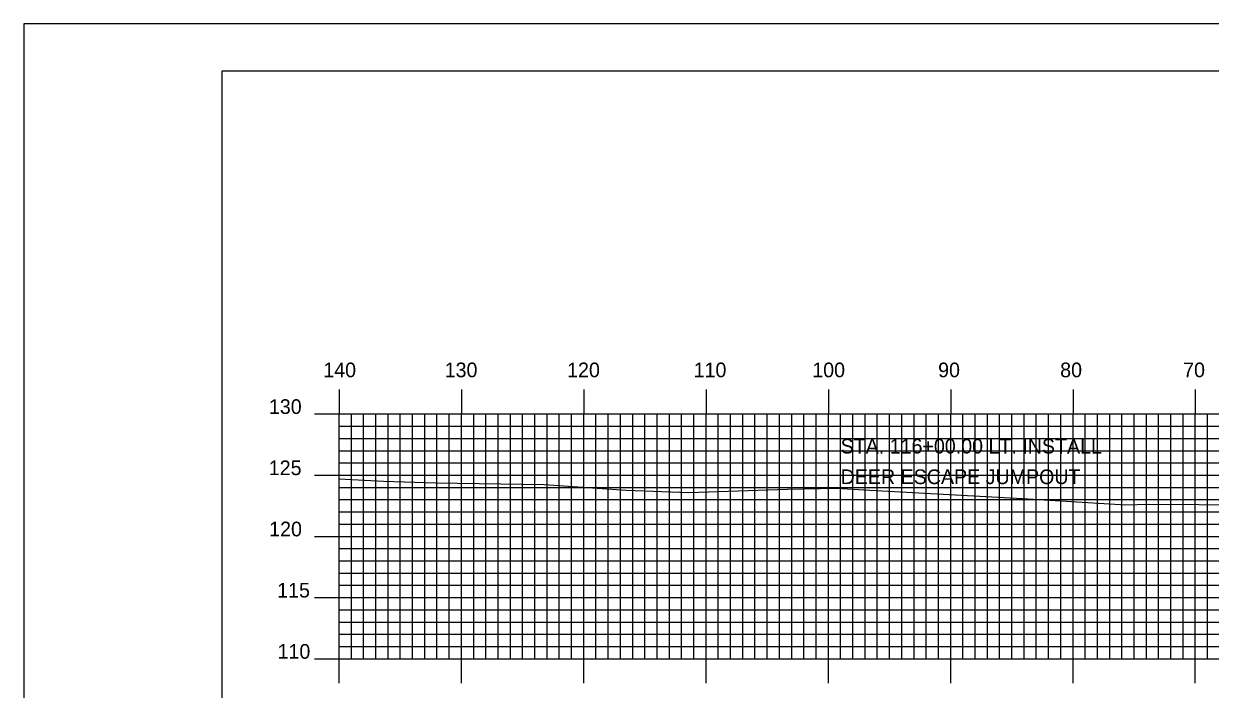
# Model space of a CAD drawing. Extents: x 1770842 to 1771185, y 442591 to 442811.
# Drawn here: x 1770841.8 to 1770938.8, y 442756.2 to 442810.5 of the extents above; entities that cross this region are included whole.
import ezdxf

# ---------------------------------------------------------------- set-up
doc = ezdxf.new("R2010")
doc.units = 0
for name, color, linetype in [('BORDER', 7, 'Continuous'), ('D_Text_Standard', 7, 'Continuous'), ('H_V ANNOTATION', 7, 'Continuous'), ('MAJOR', 7, 'Continuous'), ('MINOR', 7, 'Continuous'), ('PLOT BOUNDARY', 7, 'Continuous'), ('S_Roadway_Centerline', 7, 'Continuous')]:
    doc.layers.add(name, color=color, linetype=linetype)

msp = doc.modelspace()

# ---------------------------------------------------------------- linework, layer by layer
at = {"layer": 'BORDER'}
msp.add_lwpolyline([(1770857.954, 442596.665), (1771177.954, 442596.665), (1771177.954, 442806.665), (1770857.954, 442806.665)], close=True, dxfattribs=at)
at = {"layer": 'MAJOR'}
for p, q in [((1770867.554, 442780.669), (1770867.554, 442778.665)), ((1770877.554, 442780.669), (1770877.554, 442778.665)), ((1770887.554, 442780.669), (1770887.554, 442778.665)), ((1770897.554, 442780.669), (1770897.554, 442778.665)), ((1770907.554, 442780.669), (1770907.554, 442778.665)), ((1770917.554, 442780.669), (1770917.554, 442778.665)), ((1770927.554, 442780.669), (1770927.554, 442778.665)), ((1770937.554, 442780.669), (1770937.554, 442778.665)), ((1770865.55, 442778.665), (1770867.554, 442778.665)), ((1770867.554, 442778.665), (1771147.554, 442778.665)), ((1770867.554, 442758.665), (1770867.554, 442778.665)), ((1770867.554, 442758.665), (1770867.554, 442778.665)), ((1770867.554, 442778.665), (1771147.554, 442778.665)), ((1770877.554, 442758.665), (1770877.554, 442778.665)), ((1770887.554, 442758.665), (1770887.554, 442778.665)), ((1770897.554, 442758.665), (1770897.554, 442778.665)), ((1770907.554, 442758.665), (1770907.554, 442778.665)), ((1770917.554, 442758.665), (1770917.554, 442778.665)), ((1770927.554, 442758.665), (1770927.554, 442778.665)), ((1770937.554, 442758.665), (1770937.554, 442778.665)), ((1770865.55, 442773.665), (1770867.554, 442773.665)), ((1770867.554, 442773.665), (1771147.554, 442773.665)), ((1770865.55, 442768.665), (1770867.554, 442768.665)), ((1770867.554, 442768.665), (1771147.554, 442768.665)), ((1770865.55, 442763.665), (1770867.554, 442763.665)), ((1770867.554, 442763.665), (1771147.554, 442763.665)), ((1770865.55, 442758.665), (1770867.554, 442758.665)), ((1770867.554, 442758.665), (1771147.554, 442758.665)), ((1770867.554, 442758.665), (1771147.554, 442758.665)), ((1770867.554, 442756.661), (1770867.554, 442758.665)), ((1770877.554, 442756.661), (1770877.554, 442758.665)), ((1770887.554, 442756.661), (1770887.554, 442758.665)), ((1770897.554, 442756.661), (1770897.554, 442758.665)), ((1770907.554, 442756.661), (1770907.554, 442758.665)), ((1770917.554, 442756.661), (1770917.554, 442758.665)), ((1770927.554, 442756.661), (1770927.554, 442758.665)), ((1770937.554, 442756.661), (1770937.554, 442758.665))]:
    msp.add_line(p, q, dxfattribs=at)
at = {"layer": 'MINOR'}
for p, q in [((1770868.554, 442758.665), (1770868.554, 442778.665)), ((1770869.554, 442758.665), (1770869.554, 442778.665)), ((1770870.554, 442758.665), (1770870.554, 442778.665)), ((1770871.554, 442758.665), (1770871.554, 442778.665)), ((1770872.554, 442758.665), (1770872.554, 442778.665)), ((1770873.554, 442758.665), (1770873.554, 442778.665)), ((1770874.554, 442758.665), (1770874.554, 442778.665)), ((1770875.554, 442758.665), (1770875.554, 442778.665)), ((1770876.554, 442758.665), (1770876.554, 442778.665)), ((1770878.554, 442758.665), (1770878.554, 442778.665)), ((1770879.554, 442758.665), (1770879.554, 442778.665)), ((1770880.554, 442758.665), (1770880.554, 442778.665)), ((1770881.554, 442758.665), (1770881.554, 442778.665)), ((1770882.554, 442758.665), (1770882.554, 442778.665)), ((1770883.554, 442758.665), (1770883.554, 442778.665)), ((1770884.554, 442758.665), (1770884.554, 442778.665)), ((1770885.554, 442758.665), (1770885.554, 442778.665)), ((1770886.554, 442758.665), (1770886.554, 442778.665)), ((1770888.554, 442758.665), (1770888.554, 442778.665)), ((1770889.554, 442758.665), (1770889.554, 442778.665)), ((1770890.554, 442758.665), (1770890.554, 442778.665)), ((1770891.554, 442758.665), (1770891.554, 442778.665)), ((1770892.554, 442758.665), (1770892.554, 442778.665)), ((1770893.554, 442758.665), (1770893.554, 442778.665)), ((1770894.554, 442758.665), (1770894.554, 442778.665)), ((1770895.554, 442758.665), (1770895.554, 442778.665)), ((1770896.554, 442758.665), (1770896.554, 442778.665)), ((1770898.554, 442758.665), (1770898.554, 442778.665)), ((1770899.554, 442758.665), (1770899.554, 442778.665)), ((1770900.554, 442758.665), (1770900.554, 442778.665)), ((1770901.554, 442758.665), (1770901.554, 442778.665)), ((1770902.554, 442758.665), (1770902.554, 442778.665)), ((1770903.554, 442758.665), (1770903.554, 442778.665)), ((1770904.554, 442758.665), (1770904.554, 442778.665)), ((1770905.554, 442758.665), (1770905.554, 442778.665)), ((1770906.554, 442758.665), (1770906.554, 442778.665)), ((1770908.554, 442758.665), (1770908.554, 442778.665)), ((1770909.554, 442758.665), (1770909.554, 442778.665)), ((1770910.554, 442758.665), (1770910.554, 442778.665)), ((1770911.554, 442758.665), (1770911.554, 442778.665)), ((1770912.554, 442758.665), (1770912.554, 442778.665)), ((1770913.554, 442758.665), (1770913.554, 442778.665)), ((1770914.554, 442758.665), (1770914.554, 442778.665)), ((1770915.554, 442758.665), (1770915.554, 442778.665)), ((1770916.554, 442758.665), (1770916.554, 442778.665)), ((1770918.554, 442758.665), (1770918.554, 442778.665)), ((1770919.554, 442758.665), (1770919.554, 442778.665)), ((1770920.554, 442758.665), (1770920.554, 442778.665)), ((1770921.554, 442758.665), (1770921.554, 442778.665)), ((1770922.554, 442758.665), (1770922.554, 442778.665)), ((1770923.554, 442758.665), (1770923.554, 442778.665)), ((1770924.554, 442758.665), (1770924.554, 442778.665)), ((1770925.554, 442758.665), (1770925.554, 442778.665)), ((1770926.554, 442758.665), (1770926.554, 442778.665)), ((1770928.554, 442758.665), (1770928.554, 442778.665)), ((1770929.554, 442758.665), (1770929.554, 442778.665)), ((1770930.554, 442758.665), (1770930.554, 442778.665)), ((1770931.554, 442758.665), (1770931.554, 442778.665)), ((1770932.554, 442758.665), (1770932.554, 442778.665)), ((1770933.554, 442758.665), (1770933.554, 442778.665)), ((1770934.554, 442758.665), (1770934.554, 442778.665)), ((1770935.554, 442758.665), (1770935.554, 442778.665)), ((1770936.554, 442758.665), (1770936.554, 442778.665)), ((1770938.554, 442758.665), (1770938.554, 442778.665)), ((1770867.554, 442777.665), (1771147.554, 442777.665)), ((1770867.554, 442777.665), (1770869.558, 442777.665)), ((1770867.554, 442776.665), (1771147.554, 442776.665)), ((1770867.554, 442776.665), (1770869.558, 442776.665)), ((1770867.554, 442775.665), (1771147.554, 442775.665)), ((1770867.554, 442775.665), (1770869.558, 442775.665)), ((1770867.554, 442774.665), (1771147.554, 442774.665)), ((1770867.554, 442774.665), (1770869.558, 442774.665)), ((1770867.554, 442772.665), (1771147.554, 442772.665)), ((1770867.554, 442772.665), (1770869.558, 442772.665)), ((1770867.554, 442771.665), (1771147.554, 442771.665)), ((1770867.554, 442771.665), (1770869.558, 442771.665)), ((1770867.554, 442770.665), (1771147.554, 442770.665)), ((1770867.554, 442770.665), (1770869.558, 442770.665)), ((1770867.554, 442769.665), (1771147.554, 442769.665)), ((1770867.554, 442769.665), (1770869.558, 442769.665)), ((1770867.554, 442767.665), (1771147.554, 442767.665)), ((1770867.554, 442767.665), (1770869.558, 442767.665)), ((1770867.554, 442766.665), (1771147.554, 442766.665)), ((1770867.554, 442766.665), (1770869.558, 442766.665)), ((1770867.554, 442765.665), (1771147.554, 442765.665)), ((1770867.554, 442765.665), (1770869.558, 442765.665)), ((1770867.554, 442764.665), (1771147.554, 442764.665)), ((1770867.554, 442764.665), (1770869.558, 442764.665)), ((1770867.554, 442762.665), (1771147.554, 442762.665)), ((1770867.554, 442762.665), (1770869.558, 442762.665)), ((1770867.554, 442761.665), (1771147.554, 442761.665)), ((1770867.554, 442761.665), (1770869.558, 442761.665)), ((1770867.554, 442760.665), (1771147.554, 442760.665)), ((1770867.554, 442760.665), (1770869.558, 442760.665)), ((1770867.554, 442759.665), (1771147.554, 442759.665)), ((1770867.554, 442759.665), (1770869.558, 442759.665))]:
    msp.add_line(p, q, dxfattribs=at)
at = {"layer": 'PLOT BOUNDARY'}
msp.add_lwpolyline([(1770841.768, 442590.547), (1771181.768, 442590.547), (1771181.768, 442810.547), (1770841.768, 442810.547)], close=True, dxfattribs=at)
at = {"layer": 'S_Roadway_Centerline'}
msp.add_lwpolyline([(1770867.554, 442773.368), (1770871.188, 442773.174), (1770875.453, 442773.034), (1770884.319, 442772.888), (1770891.012, 442772.443), (1770896.151, 442772.244), (1770904.207, 442772.512), (1770908.228, 442772.61), (1770910.452, 442772.472), (1770923.435, 442771.747), (1770931.867, 442771.25), (1770933.705, 442771.306), (1770950.297, 442771.186)], dxfattribs=at)

# ---------------------------------------------------------------- texts
at = {"layer": 'D_Text_Standard'}
for s, p in [('STA. 116+00.00 LT. INSTALL ', (1770908.554, 442775.433)), ('DEER ESCAPE JUMPOUT', (1770908.554, 442772.933))]:
    msp.add_text(s, height=1.2, dxfattribs=at).set_placement(p)
at = {"layer": 'H_V ANNOTATION'}
for s, p in [('140', (1770866.259, 442781.665)), ('130', (1770876.184, 442781.665)), ('120', (1770886.195, 442781.665)), ('110', (1770896.538, 442781.665)), ('100', (1770906.238, 442781.665)), ('90', (1770916.527, 442781.665)), ('80', (1770926.505, 442781.665)), ('70', (1770936.558, 442781.665)), ('130', (1770861.814, 442778.665)), ('125', (1770861.803, 442773.665)), ('120', (1770861.835, 442768.665)), ('115', (1770862.489, 442763.665)), ('110', (1770862.521, 442758.665))]:
    msp.add_text(s, height=1.2, dxfattribs=at).set_placement(p)
at = {"layer": 'MAJOR'}
msp.add_text('-', height=0.012, dxfattribs=at).set_placement((1770867.545, 442758.665))

doc.saveas('drawing.dxf')
